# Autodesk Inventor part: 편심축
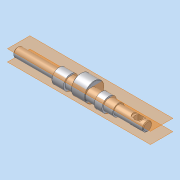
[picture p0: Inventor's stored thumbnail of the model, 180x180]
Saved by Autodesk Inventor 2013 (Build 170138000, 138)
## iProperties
Company: 한국ATC센터
Created: 2009-02
Part Number: 편심축
Document SubType Name: Modeling
Designer: KYOUNG IL JANG
Density: 7.86 g/cm^3
Mass: 246.092 g
Surface Area: 95.1288 cm^2
Volume: 31.3094 cm^3
Material: 강, 연강
Vendor: CBT Solutions
Author: KYOUNG IL JANG
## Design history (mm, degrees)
sketch "스케치1"
  geometry: L1 (-84.5, 0)-(84.5, 0); L2 (-84.5, 0)-(-84.5, 6); L3 (-84.5, 6)-(-30.5, 6); L4 (-30.5, 6)-(-30.5, 9.5); L5 (-30.5, 9.5)-(-15.5, 9.5); L6 (-15.5, 9.5)-(-15.5, 7.5); L7 (-15.5, 7.5)-(46.5, 7.5); L8 (84.5, 6)-(84.5, 0); L9 (34.5, 7.5)-(34.5, 9.5); L10 (34.5, 9.5)-(24.5, 9.5); L11 (24.5, 9.5)-(24.5, 7.5); L12 (46.5, 7.5)-(46.5, 6); L13 (46.5, 6)-(84.5, 6); 2 further points
  constraints: 26 end point, 6 parallel, 6 perpendicular, 2 point on line, 1 coincident, 1 horizontal, 1 midpoint
  dimensions: "d1" = 12 diameter of L3 L1; "d2" = 15 diameter of L7 L1; "d4" = 15 distance of L4.end L5.end; "d5" = 19 diameter of L5 L1; "d24" = 10 distance of L9.end L10.end; "d25" = 19 diameter of L10 L1; "d27" = 40 distance between parallel lines of L11 L6; "d28" = 54 distance of L2.end L3.end; "d29" = 50 distance between parallel lines of L8 L9; "d41" = 38 distance between parallel lines of L8 L12; "d42" = 12 diameter of L13 L1
revolve "회전1" stored, may be unused: angle "d6" = 90 deg
node "작업 평면1"
sketch "스케치2"
  geometry: C1 r 7.5 at (0, 0) reference; C2 r 12.5 at (0, 4.5); 1 further point
  constraints: 1 centre point, 1 vertical alignment
  dimensions: "d8" = 4.5 distance of point (0, 0) C2.centre; "d9" = 25 diameter of C2
extrude "돌출1" join sketch "스케치2" distance "d10" = 18; taper "d11" = 0 deg
chamfer "모따기1" distance "d12" = 1; stored, may be unused: second distance "d13" = 2, angle "d14" = 45 deg
chamfer "모따기2" distance "d15" = 0.5; stored, may be unused: second distance "d16" = 2, angle "d17" = 45 deg
node "작업 평면2"
sketch "스케치3"
  geometry: L1 (4, -2)-(18, -2); L2 (18, 2)-(4, 2); L3 (27, 5)-(27, -5) reference; A1 r 2 centre (18, 0) between (18, -2) and (18, 2); A2 r 2 centre (4, 0) between (4, 2) and (4, -2); 2 further points
  constraints: 4 end point, 4 point on circle, 4 tangent, 2 centre point, 1 horizontal, 1 horizontal alignment, 1 midpoint, 1 parallel
  dimensions: "d18" = 7 distance edge to line of A1 L3; "d19" = 4 distance between parallel lines of L2 L1; "d20" = 18 dimension on A1 A2
extrude "돌출2" cut sketch "스케치3" distance "d21" = 2.5; taper "d22" = 0 deg
revolve "회전2" stored, may be unused: angle "d26" = 90 deg
node "작업 평면3"
sketch "스케치4"
  geometry: L1 (44, 5)-(44, -5) reference; 2 further points
  constraints: 1 horizontal alignment
  dimensions: "d30" = 12 distance from line of point (32, 0) L1
hole "구멍1" sketch "스케치4" at (32, 0) diameter "d31" = 9; stored, may be unused: countersink angle "d35" = 90 deg, drill point angle "d37" = 118 deg; dims "d32" = 6, "d33" = 14, "d34" = 3, "d36" = 8
node "작업 평면4"
sketch "스케치5"
  geometry: C1 r 8 at (32, 0); A1 r 4.5 centre (32, 0) between (29.879, 3.969) and (29.879, -3.969) reference; A2 r 4.5 centre (32, 0) between (34.121, -3.969) and (34.121, 3.969) reference; 1 further point
  constraints: 2 horizontal alignment, 1 centre point, 1 coincident
  dimensions: "d38" = 16 diameter of C1
extrude "돌출3" cut sketch "스케치5" distance "d39" = 3; taper "d40" = 0 deg
node "솔리드1"
node "투영된 루프1"
other parameters: "d7" = 8.5
